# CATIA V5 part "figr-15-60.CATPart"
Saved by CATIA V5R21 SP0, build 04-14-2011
Part number: Part1
Bounding box of the stored display mesh (mm): x -35.944 to 35.944, y -33.497 to 33.497, z 0 to 50.428
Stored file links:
  C:\Users\CADCIM\CATIA_v5r21\c15_cat_v5r21\c15-catia-v5r20-prt\Part2.CATPart
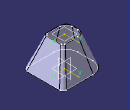
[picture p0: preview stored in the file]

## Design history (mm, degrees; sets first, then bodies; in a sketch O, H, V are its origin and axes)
SheetMetalParameters1: Thickness 1, BendRadius 2, KFactor 0.400515 {= log(min(100,max(20*SheetMetalParameters1.BendRadius,SheetMetalParameters1.Thickness)/SheetMetalParameters1.Thickness))/log(100)/2}, ReliefRadialLength 1, ReliefAxialLength 2, MinimumBendRadius 0
Body1 (main body)
  Sketch1 on xy-plane, origin (0, 0, 0), H (1, 0, 0), V (0, 1, 0)
    line L1 (-15, -32.5532) -> (30, -32.5532)
    line L2 (35, -27.5532) -> (35, 27.5532)
    line L3 (30, 32.5532) -> (-15, 32.5532)
    line L4 (-35, 12.5532) -> (-35, -12.5532)
    arc A1 centre (-15, -12.5532) radius 20 from (-35, -12.5532) to (-15, -32.5532) ccw
    arc A2 centre (-15, 12.5532) radius 20 from (-35, 12.5532) to (-15, 32.5532) cw
    arc A3 centre (30, -27.5532) radius 5 from (30, -32.5532) to (35, -27.5532) ccw
    arc A4 centre (30, 27.5532) radius 5 from (35, 27.5532) to (30, 32.5532) ccw
    radius A1 = 20
    radius A2 = 20
    radius A3 = 5
    radius A4 = 5
    distance L2 L4 = 70
    horizontal: L1 H, L3 H
    vertical: L2 V, L4 V
    tangency: A1 L4, A1 L1, A2 L4, A2 L3, A3 L1, A3 L2, A4 L2, A4 L3
    symmetry: L3 L1 H, L4 L2 V
  Plane1: type Offset, RefPlane xy-plane, Offset 50
  Sketch2 "Sketch.2" on Plane1, origin (0, 0, 50), H (1, 0, 0), V (0, 1, 0)
    line L1 (-7.5, 15) -> (14.5, 15)
    line L2 (17.5, 12) -> (17.5, -12)
    line L3 (14.5, -15) -> (-7.5, -15)
    line L4 (-17.5, -5) -> (-17.5, 5)
    arc A1 centre (-7.5, -5) radius 10 from (-7.5, -15) to (-17.5, -5) cw
    arc A2 centre (-7.5, 5) radius 10 from (-17.5, 5) to (-7.5, 15) cw
    arc A3 centre (14.5, 12) radius 3 from (14.5, 15) to (17.5, 12) cw
    arc A4 centre (14.5, -12) radius 3 from (17.5, -12) to (14.5, -15) cw
    radius A1 = 10
    radius A2 = 10
    radius A3 = 3
    radius A4 = 3
    distance L4 L2 = 35
    distance L1 L3 = 30
    horizontal: L1 H, L3 H
    vertical: L2 V, L4 V
    tangency: A1 L3, A1 L4, A2 L4, A2 L1, A3 L1, A3 L2, A4 L2, A4 L3
    symmetry: L4 L2 V, L1 L3 H
  Hopper1: HopperFixedSideType 0, HopperType 0, Hopper_InvariantPoint vertex [element of Sketch1 | element of Sketch1], Hopper_NeutralFiber 0, Hopper_ReferenceEdge edge [face of Hopper1 | face of Hopper1], Hopper_Surface {loft Sections (Sketch1; Sketch2), SectionCouplingPoints ({coupling CouplingPoints (vertex [element of Sketch1 | element of Sketch1]; vertex [element of Sketch2 | element of Sketch2])}; {coupling CouplingPoints (vertex [element of Sketch1 | element of Sketch1]; vertex [element of Sketch2 | element of Sketch2])}; {coupling CouplingPoints (vertex [element of Sketch1 | element of Sketch1]; vertex [element of Sketch2 | element of Sketch2])}; {coupling CouplingPoints (vertex [element of Sketch1 | element of Sketch1]; vertex [element of Sketch2 | element of Sketch2])}; {coupling CouplingPoints (vertex [element of Sketch1 | element of Sketch1]; vertex [element of Sketch2 | element of Sketch2])}; {coupling CouplingPoints (vertex [element of Sketch1 | element of Sketch1]; vertex [element of Sketch2 | element of Sketch2])}; {coupling CouplingPoints (vertex [element of Sketch1 | element of Sketch1]; vertex [element of Sketch2 | element of Sketch2])}; {coupling CouplingPoints (vertex [element of Sketch1 | element of Sketch1]; vertex [element of Sketch2 | element of Sketch2])})}, Hopper_TearWires edge [face of Hopper1 | face of Hopper1], Hopper_Thickness 1, KFacteur 0.400515 {= SheetMetalParameters1.KFactor}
